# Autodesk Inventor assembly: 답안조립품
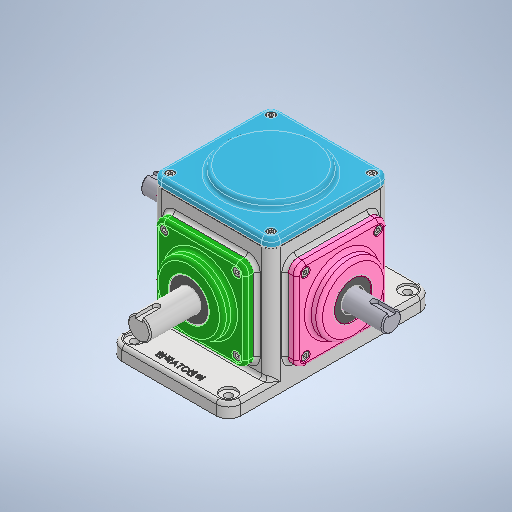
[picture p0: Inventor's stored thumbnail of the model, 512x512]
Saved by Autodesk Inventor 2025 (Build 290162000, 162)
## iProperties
Created: 2024-08
Part Number: 답안조립품
Document SubType Name: Assembly
Designer: rese9
Author: rese9
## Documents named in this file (15)
- C:\Users\rese9\OneDrive\바탕 화면\640807V1010\답안조립품.iam
- C:\Users\rese9\OneDrive\바탕 화면\640807V1010\본체\본체.ipt
- C:\Users\rese9\OneDrive\바탕 화면\640807V1010\개스킷\개스킷.ipt
- C:\Users\rese9\OneDrive\바탕 화면\640807V1010\메인베벨기어\메인베벨기어.ipt
- C:\Users\rese9\OneDrive\바탕 화면\640807V1010\메인축\메인축.ipt
- C:\Users\rese9\OneDrive\바탕 화면\640807V1010\메인커버\메인커버.ipt
- C:\Users\rese9\OneDrive\바탕 화면\640807V1010\베어링 6203\베어링 6203.ipt
- C:\Users\rese9\OneDrive\바탕 화면\640807V1010\베어링 6204\베어링 6204.ipt
- C:\Users\rese9\OneDrive\바탕 화면\640807V1010\볼트 M4\볼트 M4.ipt
- C:\Users\rese9\OneDrive\바탕 화면\640807V1010\상부커버\상부커버.ipt
- C:\Users\rese9\OneDrive\바탕 화면\640807V1010\서브베벨기어\서브베벨기어.ipt
- C:\Users\rese9\OneDrive\바탕 화면\640807V1010\서브축\서브축.ipt
- C:\Users\rese9\OneDrive\바탕 화면\640807V1010\서브커버\서브커버.ipt
- C:\Users\rese9\OneDrive\바탕 화면\640807V1010\오일 실 20 35 8\오일 실 20 35 8.ipt
- C:\Users\rese9\OneDrive\바탕 화면\640807V1010\키 4x4\키 4x4.ipt
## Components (1 placed, 1 different names)
1. 개스킷:1
## Named parameters: d13_d0 = 0, d14_d1 = 0, d15_d2 = 0, d16_d3 = 0, d17_d6 = 0, d18_d7 = 0, d19_d8 = 180 deg
